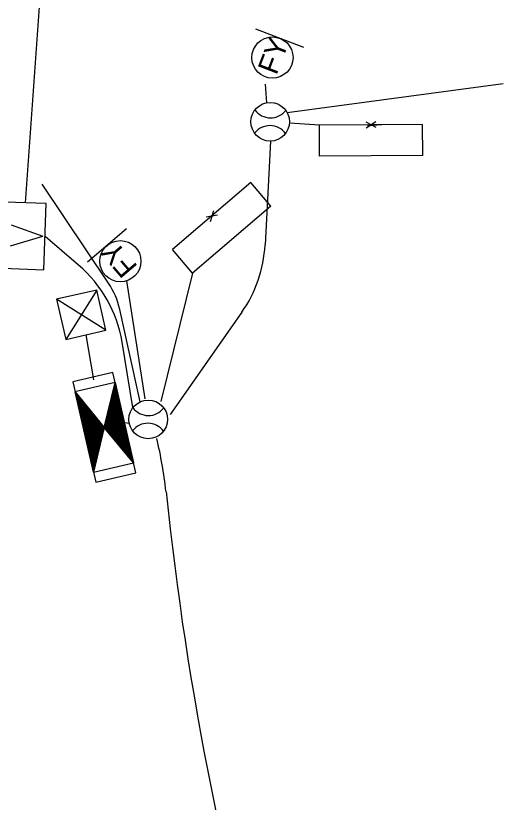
# Model space of a CAD drawing. Extents: x 601462 to 605493, y 331960 to 402715.
# Drawn here: x 603992 to 604086.6, y 339139.5 to 339292.1 of the extents above; entities that cross this region are included whole.
import ezdxf

# ---------------------------------------------------------------- set-up
doc = ezdxf.new("R2010")
doc.units = 0
doc.layers.add('P_FTMS', color=7, linetype='Continuous')
doc.layers.add('P_FTMSConduit', color=7, linetype='Continuous')

# ---------------------------------------------------------------- blocks, each defined once
blk = doc.blocks.new('FCB')
at = {"layer": 'P_FTMS'}
for p, q in [((-48.28, 24.13), (-48.04, 24.37)), ((-45.5, 22.74), (-47.13, 24.37)), ((-46.9, 23.45), (-45.97, 24.37)), ((-45.53, 22.75), (-43.9, 24.37)), ((-41.37, 20.68), (-45.06, 24.37)), ((-44.14, 22.06), (-41.83, 24.37)), ((-37.23, 18.61), (-43, 24.37)), ((-42.76, 21.38), (-39.76, 24.37)), ((-41.39, 20.69), (-37.69, 24.37)), ((-33.1, 16.54), (-40.93, 24.37)), ((-40.01, 20), (-35.63, 24.37)), ((-28.96, 14.47), (-38.86, 24.37)), ((-38.63, 19.31), (-33.56, 24.37)), ((-37.25, 18.62), (-31.49, 24.38)), ((-24.82, 12.41), (-36.79, 24.37)), ((-35.87, 17.93), (-29.42, 24.38)), ((-20.68, 10.34), (-34.72, 24.37)), ((-34.49, 17.24), (-27.35, 24.38)), ((-33.11, 16.55), (-25.28, 24.38)), ((-16.55, 8.27), (-32.65, 24.37)), ((-31.73, 15.86), (-23.21, 24.38)), ((-12.41, 6.2), (-30.58, 24.38)), ((-30.35, 15.17), (-21.14, 24.38)), ((-28.97, 14.48), (-19.07, 24.38)), ((-8.27, 4.14), (-28.51, 24.38)), ((-27.59, 13.79), (-17, 24.38)), ((-4.14, 2.07), (-26.45, 24.38)), ((-26.21, 13.1), (-14.94, 24.38)), ((-24.83, 12.41), (-12.87, 24.38)), ((0, 0), (-24.38, 24.38)), ((-23.45, 11.72), (-10.8, 24.38)), ((1.38, 0.69), (-22.31, 24.38)), ((-22.07, 11.03), (-8.73, 24.38)), ((-20.69, 10.34), (-6.66, 24.38)), ((2.76, 1.38), (-20.24, 24.38)), ((-19.31, 9.65), (-4.59, 24.38)), ((4.14, 2.07), (-18.17, 24.38)), ((-17.93, 8.96), (-2.52, 24.38)), ((-16.55, 8.28), (-0.45, 24.38)), ((5.52, 2.76), (-16.1, 24.38)), ((-15.18, 7.58), (1.62, 24.38)), ((6.9, 3.45), (-14.03, 24.38)), ((-13.8, 6.89), (3.69, 24.38)), ((-12.41, 6.21), (5.76, 24.38)), ((8.28, 4.14), (-11.96, 24.38)), ((-11.04, 5.52), (7.83, 24.38)), ((9.66, 4.83), (-9.89, 24.38)), ((-9.66, 4.83), (9.9, 24.38)), ((-8.28, 4.14), (11.97, 24.38)), ((11.03, 5.52), (-7.83, 24.38)), ((-6.9, 3.45), (14.04, 24.38)), ((12.41, 6.21), (-5.76, 24.38)), ((-5.52, 2.76), (16.11, 24.38)), ((-4.14, 2.07), (18.18, 24.38)), ((13.79, 6.9), (-3.69, 24.38)), ((-2.76, 1.38), (20.24, 24.38)), ((15.17, 7.59), (-1.62, 24.38)), ((-1.38, 0.69), (22.31, 24.38)), ((0, 0), (24.38, 24.38)), ((16.55, 8.28), (0.45, 24.38)), ((17.93, 8.97), (2.52, 24.38)), ((4.14, 2.07), (26.45, 24.38)), ((19.31, 9.66), (4.59, 24.38)), ((20.69, 10.34), (6.66, 24.38)), ((8.28, 4.14), (28.52, 24.38)), ((22.07, 11.04), (8.72, 24.38)), ((23.45, 11.73), (10.79, 24.38)), ((12.41, 6.21), (30.59, 24.38)), ((24.83, 12.41), (12.86, 24.38)), ((26.21, 13.1), (14.93, 24.38)), ((16.55, 8.28), (32.66, 24.38)), ((27.59, 13.8), (17, 24.38)), ((28.97, 14.48), (19.07, 24.38)), ((20.69, 10.35), (34.73, 24.38)), ((30.35, 15.17), (21.14, 24.38)), ((31.72, 15.86), (23.21, 24.38)), ((24.83, 12.41), (36.8, 24.38)), ((33.1, 16.55), (25.27, 24.38)), ((34.48, 17.24), (27.34, 24.38)), ((28.97, 14.48), (38.87, 24.38)), ((35.86, 17.93), (29.41, 24.38)), ((37.24, 18.62), (31.48, 24.38)), ((33.11, 16.55), (40.93, 24.38)), ((38.62, 19.31), (33.55, 24.38)), ((40, 20), (35.62, 24.38)), ((37.25, 18.62), (43, 24.38)), ((41.38, 20.69), (37.69, 24.38)), ((42.76, 21.38), (39.76, 24.38)), ((41.38, 20.69), (45.07, 24.38)), ((44.14, 22.07), (41.83, 24.38)), ((45.52, 22.76), (43.89, 24.38)), ((45.52, 22.76), (47.14, 24.38)), ((46.9, 23.45), (45.96, 24.38)), ((48.28, 24.14), (48.03, 24.38)), ((-24.4, -24.4), (0, 0)), ((24.4, -24.4), (0, 0)), ((-32.68, -24.4), (-16.56, -8.28)), ((-30.61, -24.4), (-12.42, -6.21)), ((-28.54, -24.4), (-8.28, -4.14)), ((-26.47, -24.4), (-4.14, -2.07)), ((-22.33, -24.4), (1.38, -0.69)), ((-20.26, -24.4), (2.76, -1.38)), ((-18.19, -24.4), (4.14, -2.07)), ((-2.5, -24.4), (-17.93, -8.97)), ((-0.43, -24.4), (-16.55, -8.28)), ((-16.12, -24.4), (5.52, -2.76)), ((1.64, -24.4), (-15.17, -7.59)), ((-14.05, -24.4), (6.9, -3.45)), ((3.71, -24.4), (-13.79, -6.9)), ((5.78, -24.4), (-12.41, -6.21)), ((-11.99, -24.4), (8.28, -4.14)), ((7.85, -24.4), (-11.03, -5.52)), ((-9.92, -24.4), (9.66, -4.83)), ((9.92, -24.4), (-9.66, -4.83)), ((11.98, -24.4), (-8.28, -4.14)), ((-7.85, -24.4), (11.03, -5.52)), ((14.05, -24.4), (-6.9, -3.45)), ((-5.78, -24.4), (12.41, -6.21)), ((16.12, -24.4), (-5.52, -2.76)), ((18.19, -24.4), (-4.14, -2.07)), ((-3.71, -24.4), (13.79, -6.9)), ((20.26, -24.4), (-2.76, -1.38)), ((-1.64, -24.4), (15.17, -7.59)), ((22.33, -24.4), (-1.38, -0.69)), ((0.43, -24.4), (16.55, -8.28)), ((2.5, -24.4), (17.93, -8.97)), ((26.47, -24.4), (4.14, -2.07)), ((28.53, -24.4), (8.28, -4.14)), ((30.6, -24.4), (12.41, -6.21)), ((32.67, -24.4), (16.55, -8.28)), ((-40.96, -24.41), (-33.12, -16.56)), ((-38.89, -24.41), (-28.97, -14.49)), ((-36.82, -24.41), (-24.84, -12.42)), ((-29.39, -24.4), (-35.86, -17.93)), ((-34.75, -24.4), (-20.7, -10.35)), ((-27.32, -24.4), (-34.48, -17.25)), ((-25.26, -24.4), (-33.1, -16.56)), ((-23.19, -24.4), (-31.72, -15.86)), ((-21.12, -24.4), (-30.34, -15.18)), ((-19.05, -24.4), (-28.97, -14.49)), ((-16.98, -24.4), (-27.58, -13.8)), ((-14.91, -24.4), (-26.21, -13.11)), ((-12.84, -24.4), (-24.83, -12.42)), ((-10.77, -24.4), (-23.45, -11.73)), ((-8.71, -24.4), (-22.07, -11.04)), ((-6.64, -24.4), (-20.69, -10.35)), ((-4.57, -24.4), (-19.31, -9.66)), ((4.57, -24.4), (19.31, -9.66)), ((6.64, -24.4), (20.69, -10.34)), ((8.71, -24.4), (22.07, -11.04)), ((10.77, -24.4), (23.45, -11.73)), ((12.84, -24.4), (24.83, -12.41)), ((14.91, -24.4), (26.21, -13.11)), ((16.98, -24.4), (27.59, -13.8)), ((19.05, -24.4), (28.97, -14.48)), ((34.74, -24.4), (20.69, -10.35)), ((21.12, -24.4), (30.35, -15.17)), ((23.19, -24.4), (31.72, -15.86)), ((36.81, -24.39), (24.83, -12.42)), ((25.26, -24.4), (33.1, -16.55)), ((27.33, -24.4), (34.48, -17.24)), ((38.88, -24.39), (28.97, -14.49)), ((29.4, -24.4), (35.86, -17.93)), ((40.95, -24.39), (33.11, -16.56)), ((-48.01, -24.41), (-48.27, -24.14)), ((-47.16, -24.41), (-45.53, -22.77)), ((-45.94, -24.41), (-46.89, -23.45)), ((-43.87, -24.41), (-45.52, -22.77)), ((-45.1, -24.41), (-41.39, -20.7)), ((-41.81, -24.41), (-44.14, -22.07)), ((-43.03, -24.41), (-37.26, -18.63)), ((-39.74, -24.41), (-42.76, -21.38)), ((-37.67, -24.41), (-41.38, -20.7)), ((-35.6, -24.4), (-40, -20)), ((-33.53, -24.4), (-38.62, -19.32)), ((-31.46, -24.4), (-37.24, -18.63)), ((31.47, -24.4), (37.24, -18.62)), ((33.54, -24.4), (38.62, -19.31)), ((35.61, -24.4), (40, -20)), ((43.02, -24.39), (37.25, -18.63)), ((37.68, -24.39), (41.38, -20.69)), ((39.75, -24.39), (42.76, -21.38)), ((45.08, -24.39), (41.39, -20.7)), ((41.82, -24.39), (44.14, -22.07)), ((43.89, -24.39), (45.52, -22.76)), ((47.15, -24.39), (45.53, -22.77)), ((45.95, -24.39), (46.9, -23.45)), ((48.02, -24.39), (48.28, -24.14))]:
    blk.add_line(p, q, dxfattribs=at)
for points in [[(60.95, 24.38), (-60.96, 24.37), (-60.96, -24.41), (60.96, -24.39)], [(48.77, 24.39), (-48.77, 24.37), (-48.76, -24.41), (48.78, -24.39)], [(48.77, 24.38), (0, 0), (-48.77, 24.37)], [(48.78, -24.39), (-48.8, -24.41), (0, 0)]]:
    blk.add_lwpolyline(points, close=True, dxfattribs=at)
blk = doc.blocks.new('FMB_1')
at = {"layer": 'P_FTMS'}
for p, q in [((24.38, -24.38), (-24.38, 24.38)), ((-24.38, -24.38), (24.38, 24.38))]:
    blk.add_line(p, q, dxfattribs=at)
blk.add_lwpolyline([(24.38, -24.38), (24.38, 24.38), (-24.38, 24.38), (-24.38, -24.38)], close=True, dxfattribs=at)
blk = doc.blocks.new('_U227')
at = {"layer": 'P_FTMS'}
for p, q in [((30.41, 9.38), (-30.55, 8.9)), ((30.55, -8.91), (30.41, 9.38)), ((-30.41, -9.38), (-30.55, 8.9)), ((30.55, -8.91), (-30.41, -9.38))]:
    blk.add_line(p, q, dxfattribs=at)
blk = doc.blocks.new('FFY')
at = {"layer": 'P_FTMS'}
blk.add_line((24.38, -30.48), (24.38, 30.48), dxfattribs=at)
blk.add_circle((0, 0), 24.38, dxfattribs=at)
blk.add_text('FY', height=24.384, dxfattribs=at).set_placement((-18.49, -12.19))
blk = doc.blocks.new('FTMS_FCV')
at = {"layer": 'P_FTMS'}
blk.add_line((12.74, 16.25), (0.59, -21.86), dxfattribs=at)
blk.add_lwpolyline([(39.1, 24.39), (-39.1, 24.38), (-39.1, -24.4), (39.11, -24.39)], close=True, dxfattribs=at)
blk.add_lwpolyline([(-12.06, 16.23), (0.59, -21.86)], dxfattribs=at)

msp = doc.modelspace()

# ---------------------------------------------------------------- linework, layer by layer
at = {"layer": 'P_FTMS'}
for p, q in [((604050.9, 339270.87), (604045.1, 339271.29)), ((604063.92, 339271.03), (604060.26, 339270.77)), ((604026.29, 339242.2), (604020.13, 339217.26))]:
    msp.add_line(p, q, dxfattribs=at)
for centre in [(604041.35, 339271.56), (604017.68, 339213.79)]:
    msp.add_circle(centre, 3.75, dxfattribs=at)
for centre, start, end in [((604041.41, 339276.06), 216.2095, 322.4651), ((604041.3, 339267.06), 36.2095, 142.4651), ((604017.73, 339218.29), 216.2095, 322.4651), ((604017.62, 339209.29), 36.2095, 142.4651)]:
    msp.add_arc(centre, 3.75, start, end, dxfattribs=at)
at = {"layer": 'P_FTMSConduit'}
for p, q in [((603993.89, 339255.8), (604012.99, 339528.12)), ((604044.63, 339273.38), (604086.55, 339278.98)), ((604040.41, 339278.84), (604040.61, 339275.24)), ((604061.93, 339270.43), (604059.95, 339271.5)), ((604061.86, 339271.56), (604060.01, 339270.29)), ((604009.96, 339240.22), (603997.07, 339259.43)), ((604031.11, 339253.45), (604028.9, 339253.04)), ((604030.35, 339254.29), (604029.7, 339252.14)), ((604004.16, 339243.73), (603997.67, 339249.26)), ((604017.11, 339217.77), (604013.51, 339240.69)), ((604016.13, 339217.17), (604012.15, 339235.11)), ((604005.58, 339230.19), (604007.04, 339221.45)), ((604014.7, 339216.08), (604012.6, 339228.79)), ((604014.11, 339212.97), (604013.06, 339213.13))]:
    msp.add_line(p, q, dxfattribs=at)
for points in [[(604041.4, 339267.81), (604040.35, 339247.65)], [(604035.84, 339234.57), (604021.91, 339214.76)]]:
    msp.add_lwpolyline(points, dxfattribs=at)
for centre, radius, start, end in [((604015.39, 339248.95), 25, 324.8835, 357.0207), ((603987.94, 339224.7), 25, 9.3958, 49.5431), ((603997.51, 339231.86), 15, 12.4924, 33.8671), ((603942.04, 339191.57), 79.49, 5.958, 13.4818), ((604640.25, 339264.43), 622.48, 185.95802, 207.38381)]:
    msp.add_arc(centre, radius, start, end, dxfattribs=at)

# ---------------------------------------------------------------- block references
at = {"layer": 'P_FTMS'}
for name, p, xscale, yscale, rotation in [('FFY', (604041.79, 339284.03), 0.16404166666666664, 0.1640416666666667, 68.87537191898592), ('_U227', (604031.94, 339250.98), 0.32808333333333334, 0.3280833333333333, 40.12301998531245), ('FTMS_FCV', (603993.67, 339249.39), 0.16404166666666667, 0.16404166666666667, 88.04112391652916), ('FFY', (604012.28, 339244.49), 0.16404166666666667, 0.16404166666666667, 130.4251150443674), ('FMB_1', (604004.69, 339234.09), 0.1640416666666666, 0.16404166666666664, 102.94164813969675), ('FCB', (604009.16, 339212.24), 0.1640416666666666, 0.16404166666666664, 102.94164813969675)]:
    msp.add_blockref(name, p, dxfattribs=dict(at, xscale=xscale, yscale=yscale, rotation=rotation))
at = {"layer": 'P_FTMS', "xscale": 0.32808333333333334, "yscale": 0.32808333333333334}
msp.add_blockref('_U227', (604060.93, 339267.95), dxfattribs=at)

doc.saveas('drawing.dxf')
